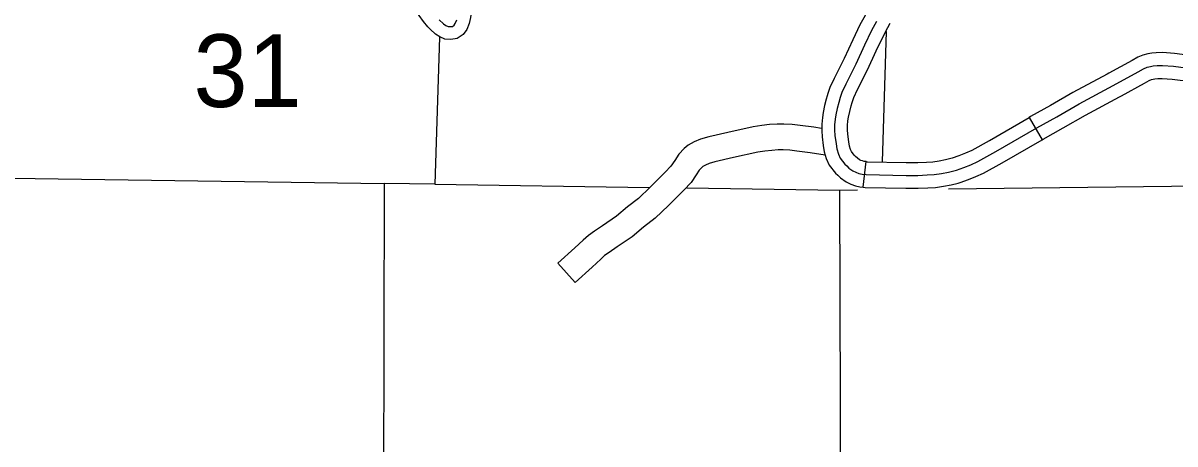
# Model space of a CAD drawing. Extents: x -3711 to 825, y -151 to 1050.
# Drawn here: x -2947.9 to -2872.9, y 243.7 to 271.1 of the extents above; entities that cross this region are included whole.
import ezdxf

# ---------------------------------------------------------------- set-up
doc = ezdxf.new("R2010")
doc.units = 0
for name, color, linetype in [('Level 31', 7, 'Continuous'), ('Level 4', 7, 'Continuous'), ('Level 46', 7, 'Continuous'), ('Level 5', 7, 'Continuous'), ('Level 8', 7, 'Continuous')]:
    doc.layers.add(name, color=color, linetype=linetype)

msp = doc.modelspace()

# ---------------------------------------------------------------- linework, layer by layer
at = {"layer": 'Level 31'}
for p, q in [((-2882.429, 264.987), (-2881.585, 263.533)), ((-2893.23, 260.438), (-2893.031, 262.108)), ((-2893.23, 260.438), (-2893.23, 260.438))]:
    msp.add_line(p, q, dxfattribs=at)
for points in [[(-2918.736, 274.334), (-2918.722, 272.778), (-2918.722, 272.5), (-2918.732, 272.174), (-2918.754, 271.832), (-2918.79, 271.504), (-2918.879, 271.109), (-2919.024, 270.705), (-2919.261, 270.381), (-2919.656, 270.117), (-2920.057, 270.055), (-2920.451, 270.081), (-2920.791, 270.24), (-2921.06, 270.414), (-2921.416, 270.734), (-2921.56, 270.878), (-2921.845, 271.233), (-2922.12, 271.619), (-2922.357, 271.95)], [(-2892.974, 271.901), (-2893.111, 271.634), (-2893.441, 271.021), (-2893.9, 270.043), (-2894.473, 268.827), (-2895.121, 267.519), (-2895.392, 266.927), (-2895.534, 266.55), (-2895.576, 266.396)], [(-2920.837, 271.344), (-2920.547, 271.083), (-2920.383, 270.977), (-2920.238, 270.909), (-2920.093, 270.9), (-2919.968, 270.919), (-2919.852, 270.996), (-2919.775, 271.103), (-2919.688, 271.344)], [(-2892.367, 271.243), (-2892.69, 270.643), (-2893.139, 269.685), (-2893.716, 268.462), (-2894.362, 267.157), (-2894.616, 266.603), (-2894.733, 266.292), (-2894.823, 265.958), (-2894.927, 265.564), (-2895.008, 265.149), (-2895.054, 264.868), (-2895.089, 264.502), (-2895.089, 264.145), (-2895.066, 263.81), (-2894.995, 263.273), (-2894.938, 262.93), (-2894.847, 262.598), (-2894.72, 262.321), (-2894.425, 261.943), (-2894.304, 261.836), (-2894.156, 261.686), (-2893.901, 261.501), (-2893.716, 261.409), (-2893.508, 261.34), (-2893.301, 261.293), (-2893.041, 261.263)], [(-2893.952, 265.959), (-2893.932, 266.034), (-2893.839, 266.28), (-2893.603, 266.796), (-2892.959, 268.096), (-2892.379, 269.327), (-2891.938, 270.265), (-2891.622, 270.853), (-2891.477, 271.136)], [(-2871.11, 268.906), (-2871.489, 268.959), (-2872.962, 269.16), (-2873.745, 269.211), (-2874.16, 269.2), (-2874.449, 269.172), (-2874.705, 269.136), (-2875.021, 269.049), (-2875.348, 268.908), (-2875.731, 268.704), (-2877.241, 267.868)], [(-2893.041, 261.263), (-2890.44, 261.213), (-2889.667, 261.213), (-2889.068, 261.236), (-2888.606, 261.259), (-2888.145, 261.328), (-2887.684, 261.42), (-2887.169, 261.545), (-2886.68, 261.721), (-2886.23, 261.905), (-2885.772, 262.109), (-2884.592, 262.759), (-2881.928, 264.306), (-2880.624, 265.033), (-2879.171, 265.876), (-2876.956, 267.065), (-2875.33, 267.965), (-2874.984, 268.15), (-2874.742, 268.254), (-2874.534, 268.312), (-2874.351, 268.337), (-2874.109, 268.36), (-2873.761, 268.369), (-2873.046, 268.323), (-2871.604, 268.127)], [(-2877.241, 267.868), (-2877.359, 267.803), (-2879.581, 266.61), (-2881.04, 265.764), (-2882.344, 265.037), (-2882.429, 264.987)], [(-2876.427, 266.397), (-2874.928, 267.227), (-2874.62, 267.391), (-2874.462, 267.459), (-2874.363, 267.487), (-2874.254, 267.502), (-2874.058, 267.52), (-2873.777, 267.528), (-2873.13, 267.486), (-2871.72, 267.294), (-2871.346, 267.241)], [(-2895.576, 266.396), (-2895.635, 266.175), (-2895.747, 265.752), (-2895.836, 265.296), (-2895.888, 264.975), (-2895.929, 264.543), (-2895.929, 264.116), (-2895.903, 263.726), (-2895.827, 263.149), (-2895.76, 262.749), (-2895.639, 262.309), (-2895.443, 261.882), (-2895.04, 261.364), (-2894.882, 261.224), (-2894.705, 261.046), (-2894.338, 260.78), (-2894.039, 260.63), (-2893.733, 260.529), (-2893.442, 260.464), (-2893.23, 260.438)], [(-2881.585, 263.533), (-2881.512, 263.576), (-2880.209, 264.303), (-2878.761, 265.142), (-2876.554, 266.327), (-2876.427, 266.397)], [(-2893.031, 262.108), (-2893.16, 262.123), (-2893.284, 262.151), (-2893.393, 262.187), (-2893.464, 262.222), (-2893.607, 262.326), (-2893.727, 262.448), (-2893.811, 262.521), (-2893.996, 262.76), (-2894.054, 262.886), (-2894.116, 263.112), (-2894.164, 263.397), (-2894.229, 263.893), (-2894.248, 264.174), (-2894.248, 264.462), (-2894.22, 264.76), (-2894.18, 265.001), (-2894.107, 265.376), (-2894.011, 265.741), (-2893.952, 265.959)], [(-2887.439, 262.344), (-2887.411, 262.351), (-2886.982, 262.505), (-2886.561, 262.678), (-2886.146, 262.863), (-2885.006, 263.491), (-2882.429, 264.987)], [(-2887.044, 260.71), (-2886.928, 260.738), (-2886.378, 260.936), (-2885.9, 261.132), (-2885.397, 261.356), (-2884.178, 262.028), (-2881.585, 263.533)], [(-2893.031, 262.108), (-2892.983, 262.102), (-2890.432, 262.053), (-2889.684, 262.053), (-2889.105, 262.076), (-2888.69, 262.096), (-2888.29, 262.156), (-2887.865, 262.241), (-2887.439, 262.344)], [(-2893.23, 260.438), (-2893.099, 260.423), (-2890.448, 260.372), (-2889.651, 260.372), (-2889.03, 260.396), (-2888.523, 260.421), (-2888, 260.5), (-2887.502, 260.599), (-2887.044, 260.71)]]:
    msp.add_lwpolyline(points, dxfattribs=at)
at = {"layer": 'Level 4'}
for points in [[(-2950.175, 261.044), (-2924.417, 260.676)], [(-2921.112, 260.629), (-2907.165, 260.43)], [(-2904.71, 260.395), (-2894.764, 260.253), (-2893.608, 260.266)], [(-2887.687, 260.337), (-2842.331, 260.874)]]:
    msp.add_lwpolyline(points, dxfattribs=at)
at = {"layer": 'Level 46'}
for points in [[(-2895.94, 264.271), (-2896.443, 264.349), (-2897.336, 264.462), (-2897.851, 264.528), (-2898.389, 264.556), (-2898.83, 264.556), (-2899.334, 264.515), (-2899.831, 264.463), (-2900.401, 264.381), (-2902.039, 264.013), (-2903.286, 263.723), (-2903.829, 263.576), (-2904.242, 263.385), (-2904.615, 263.181), (-2904.876, 262.961), (-2905.221, 262.599), (-2905.494, 262.182), (-2905.75, 261.808), (-2906.121, 261.415), (-2907.087, 260.436), (-2907.864, 259.694), (-2908.574, 259.152), (-2909.292, 258.555), (-2910.193, 257.93), (-2910.711, 257.572), (-2911.107, 257.303), (-2911.449, 256.989), (-2912.005, 256.482), (-2913.108, 255.49), (-2911.984, 254.24)], [(-2895.7, 262.532), (-2896.678, 262.684), (-2897.548, 262.794), (-2898.002, 262.853), (-2898.432, 262.875), (-2898.762, 262.875), (-2899.177, 262.841), (-2899.624, 262.794), (-2900.097, 262.726), (-2901.664, 262.374), (-2902.876, 262.092), (-2903.253, 261.99), (-2903.486, 261.882), (-2903.659, 261.788), (-2903.721, 261.735), (-2903.898, 261.55), (-2904.097, 261.246), (-2904.437, 260.75), (-2904.911, 260.248), (-2905.907, 259.238), (-2906.77, 258.414), (-2907.526, 257.837), (-2908.273, 257.216), (-2909.236, 256.548), (-2909.761, 256.185), (-2910.061, 255.981), (-2910.314, 255.749), (-2910.876, 255.236), (-2911.984, 254.24)]]:
    msp.add_lwpolyline(points, dxfattribs=at)
at = {"layer": 'Level 5'}
for points in [[(-2891.739, 270.588), (-2892.001, 262.083)], [(-2894.764, 260.253), (-2894.69, 232.222)]]:
    msp.add_lwpolyline(points, dxfattribs=at)
at = {"layer": 'Level 8'}
msp.add_lwpolyline([(-2920.796, 270.225), (-2921.112, 260.629), (-2924.417, 260.676), (-2924.536, 201.01), (-2950.769, 200.81), (-2949.901, 158.971)], dxfattribs=at)

# ---------------------------------------------------------------- texts
at = {"layer": 'Level 5'}
msp.add_text('31', height=4.7343, dxfattribs=at).set_placement((-2936.817, 265.664))

doc.saveas('drawing.dxf')
